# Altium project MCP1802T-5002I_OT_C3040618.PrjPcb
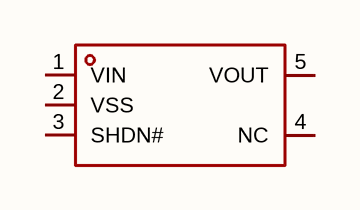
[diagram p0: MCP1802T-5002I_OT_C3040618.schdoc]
1 sheet, 1 parts. Net scope: global (net labels, ports and power ports of the same name join across sheets).

## Sheet MCP1802T-5002I_OT_C3040618.schdoc
size 127 x 101 mm

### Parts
U?  mcp1802t-5002i/ot  [SOT-23-5_L2.9-W1.6-P0.95-LS2.8-BL]  (value not drawn)

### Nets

Not connected (* = marked no-connect by the designer): U? 1(VIN) 2(VSS) 3(SHDN#) 4(NC) 5(VOUT)

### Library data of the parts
U? = mcp1802t-5002i/ot: 输出极性:正极;工作电压:10V;输出电压:5V;输出电流:300mA;电源纹波抑制比(PSRR):70dB@(10kHz);输出类型:固定;; Manufacturer: TECH PUBLIC(台舟); Symbol: MCP1802T-5002I/OT_C3040618; AddInBom: yes; ModelId: 018c57e721114987ae90467fe9f1d259; ModelTransform: 114.96,110.236,0,0,0,0,0,0,0; Output Configuration: 正极; Voltage - Supply: 10V; Output Voltage: 5V; Output Current: 300mA; Voltage Dropout: 200mV@(100mA); standby current: 25uA; Output Type: 固定; Number of Outputs: 1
